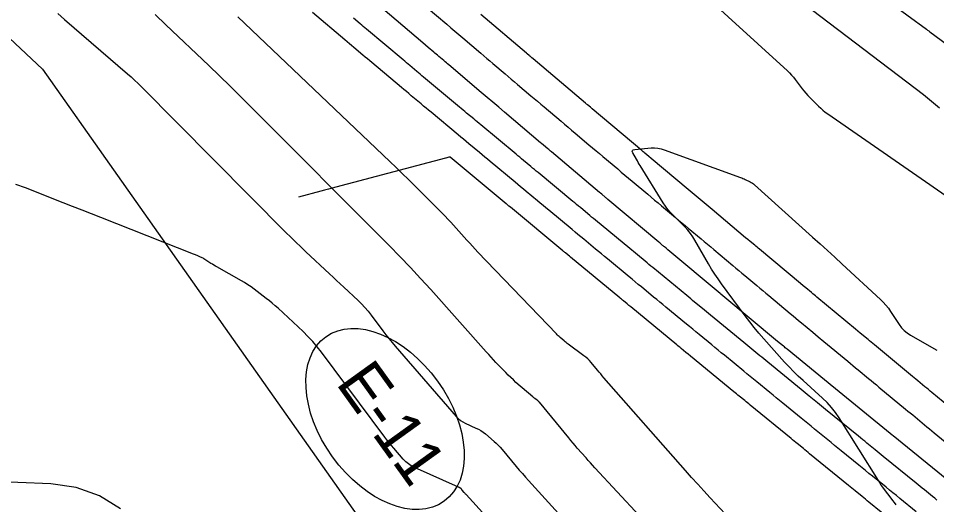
# Model space of a CAD drawing. Extents: x 1005228 to 1008882, y 1883389 to 1885754.
# Drawn here: x 1007392.6 to 1007516.7, y 1884970.9 to 1885036.6 of the extents above; entities that cross this region are included whole.
import ezdxf

# ---------------------------------------------------------------- set-up
doc = ezdxf.new("R2010")
doc.units = 0
for name, color, linetype in [('ATDIMS', 7, 'Continuous'), ('C-ANNO-NOTE', 7, 'Continuous'), ('R_Erosion', 7, 'Continuous'), ('S_BRIDGE', 7, 'Continuous'), ('TSOBSTACLE', 7, 'Continuous')]:
    doc.layers.add(name, color=color, linetype=linetype)

msp = doc.modelspace()

# ---------------------------------------------------------------- linework, layer by layer
at = {"layer": 'ATDIMS'}
msp.add_lwpolyline([(1007518.11, 1884974.26), (1007510.87, 1884980.13), (1007510.8, 1884980.19), (1007510.73, 1884980.24), (1007510.46, 1884980.47), (1007503.05, 1884986.51), (1007503, 1884986.55), (1007502.85, 1884986.68), (1007496.52, 1884991.85), (1007496.4, 1884991.95), (1007496.27, 1884992.05), (1007496.15, 1884992.16), (1007496.02, 1884992.26), (1007495.24, 1884992.91), (1007495.23, 1884992.92), (1007487.84, 1884999.08), (1007487.58, 1884999.29), (1007487.52, 1884999.34), (1007487.46, 1884999.4), (1007480.41, 1885005.29), (1007480.17, 1885005.49), (1007479.93, 1885005.69), (1007479.87, 1885005.74), (1007479.81, 1885005.79), (1007479.75, 1885005.84), (1007479.69, 1885005.89), (1007479.3, 1885006.22), (1007479.18, 1885006.33), (1007472.3, 1885012.1), (1007472.21, 1885012.18), (1007472.11, 1885012.26), (1007472.02, 1885012.33), (1007471.93, 1885012.41), (1007471.46, 1885012.8), (1007471.28, 1885012.96), (1007471.18, 1885013.04), (1007464.67, 1885018.52), (1007464.55, 1885018.63), (1007464.43, 1885018.73), (1007464.3, 1885018.83), (1007464.18, 1885018.94), (1007463.57, 1885019.45), (1007463.32, 1885019.66), (1007463.2, 1885019.76), (1007458.33, 1885023.88), (1007457.54, 1885024.55), (1007456.75, 1885025.22), (1007455.96, 1885025.89), (1007455.18, 1885026.55), (1007450.8, 1885030.27), (1007450.63, 1885030.41), (1007450.46, 1885030.56), (1007450.29, 1885030.7), (1007450.11, 1885030.85), (1007449.43, 1885031.43), (1007449.26, 1885031.57), (1007449.09, 1885031.72), (1007448.92, 1885031.86), (1007448.75, 1885032.01), (1007448, 1885032.64), (1007447.64, 1885032.95), (1007447.28, 1885033.26), (1007441.86, 1885037.87)], dxfattribs=at)
at = {"layer": 'C-ANNO-NOTE'}
for points in [[(1007517.13, 1885024.43), (1007516.05, 1885025.33), (1007514.96, 1885026.21), (1007513.85, 1885027.07), (1007499.96, 1885037.62)], [(1007397.92, 1885037.21), (1007398.85, 1885036.41), (1007407.34, 1885029.08), (1007407.83, 1885028.65), (1007408.31, 1885028.21), (1007408.78, 1885027.76), (1007409.24, 1885027.3), (1007428.76, 1885007.65), (1007429.43, 1885006.99), (1007430.11, 1885006.33), (1007430.79, 1885005.67), (1007431.48, 1885005.02), (1007434.65, 1885002.06), (1007435.14, 1885001.61), (1007435.62, 1885001.16), (1007436.1, 1885000.7), (1007436.59, 1885000.25), (1007438.52, 1884998.45), (1007439, 1884997.98), (1007439.45, 1884997.5), (1007439.88, 1884997), (1007440.28, 1884996.48), (1007441.87, 1884994.35), (1007442.28, 1884993.82), (1007442.69, 1884993.3), (1007443.11, 1884992.78), (1007443.54, 1884992.28), (1007451.78, 1884982.77), (1007452.05, 1884982.49), (1007452.35, 1884982.24), (1007452.67, 1884982.03), (1007453.01, 1884981.86), (1007454.46, 1884981.21), (1007454.81, 1884981.05), (1007455.13, 1884980.85), (1007455.45, 1884980.64), (1007455.74, 1884980.4), (1007456.91, 1884979.4), (1007457.19, 1884979.14), (1007457.47, 1884978.88), (1007457.73, 1884978.6), (1007457.98, 1884978.31), (1007459.91, 1884976), (1007460.32, 1884975.52), (1007460.73, 1884975.04), (1007461.15, 1884974.57), (1007461.57, 1884974.1), (1007466.98, 1884968.15)], [(1007488.63, 1884956.35), (1007470.54, 1884975.84), (1007470.23, 1884976.17), (1007469.93, 1884976.5), (1007469.64, 1884976.83), (1007469.34, 1884977.16), (1007468.16, 1884978.5), (1007467.87, 1884978.84), (1007467.58, 1884979.18), (1007467.29, 1884979.52), (1007467.01, 1884979.86), (1007463.03, 1884984.68), (1007462.97, 1884984.75), (1007462.9, 1884984.82), (1007462.83, 1884984.89), (1007462.75, 1884984.95), (1007462.44, 1884985.18), (1007462.36, 1884985.24), (1007462.28, 1884985.3), (1007462.21, 1884985.36), (1007462.13, 1884985.42), (1007459.87, 1884987.38), (1007459.52, 1884987.7), (1007459.17, 1884988.03), (1007458.82, 1884988.36), (1007458.49, 1884988.7), (1007457.16, 1884990.08), (1007456.83, 1884990.43), (1007456.51, 1884990.78), (1007456.18, 1884991.13), (1007455.86, 1884991.49), (1007448.35, 1884999.91), (1007446.98, 1885001.42), (1007445.6, 1885002.92), (1007444.19, 1885004.39), (1007442.76, 1885005.84), (1007424.06, 1885024.58), (1007422.64, 1885026), (1007421.21, 1885027.4), (1007419.78, 1885028.79), (1007418.33, 1885030.18), (1007412.53, 1885035.71), (1007411.09, 1885037.09)], [(1007511.27, 1884970.84), (1007511.03, 1884971.13), (1007510.8, 1884971.41), (1007510.57, 1884971.71), (1007509.69, 1884972.9), (1007509.47, 1884973.2), (1007509.26, 1884973.5), (1007509.06, 1884973.81), (1007508.86, 1884974.12), (1007503.56, 1884982.58), (1007503.07, 1884983.31), (1007502.53, 1884984), (1007501.95, 1884984.65), (1007501.31, 1884985.26), (1007498.68, 1884987.62), (1007498.03, 1884988.22), (1007497.4, 1884988.84), (1007496.79, 1884989.47), (1007496.19, 1884990.12), (1007493.38, 1884993.27), (1007492.72, 1884994.02), (1007492.09, 1884994.78), (1007491.47, 1884995.57), (1007490.86, 1884996.36), (1007487.66, 1885000.7), (1007487.19, 1885001.35), (1007486.74, 1885002.02), (1007486.32, 1885002.69), (1007485.91, 1885003.38), (1007484.06, 1885006.58), (1007483.77, 1885007.05), (1007483.45, 1885007.5), (1007483.1, 1885007.93), (1007482.72, 1885008.33), (1007481.15, 1885009.91), (1007480.77, 1885010.31), (1007480.42, 1885010.73), (1007480.09, 1885011.18), (1007479.78, 1885011.64), (1007476.66, 1885016.67), (1007476.53, 1885016.88), (1007476.4, 1885017.09), (1007476.28, 1885017.31), (1007476.16, 1885017.52), (1007475.67, 1885018.38), (1007475.59, 1885018.57), (1007475.61, 1885018.71), (1007475.72, 1885018.81), (1007475.92, 1885018.85), (1007478.15, 1885019.05), (1007478.6, 1885019.07), (1007479.04, 1885019.03), (1007479.48, 1885018.95), (1007479.91, 1885018.82), (1007490.21, 1885015.08), (1007490.38, 1885015.01), (1007490.55, 1885014.94), (1007490.71, 1885014.87), (1007490.87, 1885014.79), (1007491.52, 1885014.47), (1007491.68, 1885014.39), (1007491.83, 1885014.29), (1007491.98, 1885014.19), (1007492.11, 1885014.07), (1007499.96, 1885007.01), (1007500.97, 1885006.1), (1007501.97, 1885005.19), (1007502.97, 1885004.28), (1007503.96, 1885003.36), (1007509.15, 1884998.58), (1007509.53, 1884998.21), (1007509.88, 1884997.82), (1007510.21, 1884997.4), (1007510.52, 1884996.97), (1007511.68, 1884995.18), (1007511.99, 1884994.76), (1007512.35, 1884994.38), (1007512.75, 1884994.05), (1007513.19, 1884993.77), (1007516.77, 1884991.74)], [(1007471.72, 1884951.77), (1007453.12, 1884972.21), (1007453.06, 1884972.28), (1007453, 1884972.34), (1007452.94, 1884972.41), (1007452.88, 1884972.48), (1007452.61, 1884972.81), (1007452.57, 1884972.85), (1007452.53, 1884972.89), (1007452.49, 1884972.93), (1007452.45, 1884972.97), (1007452.29, 1884973.11), (1007452.24, 1884973.15), (1007452.2, 1884973.18), (1007452.15, 1884973.2), (1007452.1, 1884973.23), (1007446.15, 1884975.87), (1007445.72, 1884976.09), (1007445.33, 1884976.35), (1007444.96, 1884976.65), (1007444.63, 1884977), (1007443.35, 1884978.47), (1007443.04, 1884978.84), (1007442.73, 1884979.21), (1007442.43, 1884979.59), (1007442.13, 1884979.98), (1007433.58, 1884991.45), (1007433, 1884992.19), (1007432.39, 1884992.91), (1007431.75, 1884993.59), (1007431.08, 1884994.25), (1007427.7, 1884997.4), (1007427.32, 1884997.74), (1007426.93, 1884998.08), (1007426.53, 1884998.41), (1007426.12, 1884998.73), (1007424.47, 1884999.98), (1007424.06, 1885000.28), (1007423.63, 1885000.57), (1007423.19, 1885000.85), (1007422.75, 1885001.11), (1007419.43, 1885002.98), (1007419.23, 1885003.09), (1007419.03, 1885003.21), (1007418.83, 1885003.33), (1007418.64, 1885003.46), (1007417.68, 1885004.07), (1007417.57, 1885004.14), (1007417.46, 1885004.2), (1007417.35, 1885004.26), (1007417.23, 1885004.31), (1007416.76, 1885004.51), (1007416.65, 1885004.56), (1007416.53, 1885004.61), (1007416.41, 1885004.66), (1007416.29, 1885004.71), (1007403.76, 1885009.64), (1007402.49, 1885010.14), (1007401.21, 1885010.64), (1007399.93, 1885011.14), (1007398.66, 1885011.64), (1007393.55, 1885013.65), (1007392.26, 1885014.12)], [(1007406.39, 1884970.28), (1007403.57, 1884972.05), (1007400.43, 1884973.18), (1007396.98, 1884973.65), (1007365.73, 1884974.94), (1007364.86, 1884975), (1007364, 1884975.1), (1007363.14, 1884975.23), (1007362.29, 1884975.41), (1007358.9, 1884976.21), (1007358.07, 1884976.45), (1007357.28, 1884976.76), (1007356.52, 1884977.16), (1007355.81, 1884977.65), (1007334.74, 1884993.36), (1007333.77, 1884993.99), (1007332.75, 1884994.47), (1007331.67, 1884994.8), (1007330.54, 1884994.99), (1007325.89, 1884995.44), (1007324.72, 1884995.56), (1007323.57, 1884995.71)]]:
    msp.add_lwpolyline(points, dxfattribs=at)
at = {"layer": 'R_Erosion'}
msp.add_lwpolyline([(1007330.25, 1885091.31), (1007395.85, 1885029.7), (1007508, 1884870.74), (1007444.37, 1884775.26), (1007458.35, 1884766.85)], dxfattribs=at)
msp.add_ellipse((1007442.17, 1884982.43), major_axis=(8, -11.12), ratio=0.638788, dxfattribs=at)
at = {"layer": 'S_BRIDGE'}
for points in [[(1007484.55, 1885040.45), (1007496.57, 1885029.47), (1007496.85, 1885029.2), (1007497.12, 1885028.91), (1007497.37, 1885028.62), (1007497.62, 1885028.31), (1007498.56, 1885027.06), (1007498.8, 1885026.75), (1007499.05, 1885026.45), (1007499.31, 1885026.16), (1007499.58, 1885025.88), (1007500.77, 1885024.7), (1007501.06, 1885024.42), (1007501.37, 1885024.15), (1007501.69, 1885023.9), (1007502.02, 1885023.66), (1007518.62, 1885012.17)], [(1007489.49, 1884968.16), (1007486.12, 1884971.79), (1007485.28, 1884972.7), (1007484.45, 1884973.61), (1007483.62, 1884974.53), (1007482.8, 1884975.46), (1007471.76, 1884988.01), (1007471.54, 1884988.26), (1007471.32, 1884988.51), (1007471.1, 1884988.77), (1007470.89, 1884989.03), (1007470.03, 1884990.06), (1007469.81, 1884990.31), (1007469.58, 1884990.55), (1007469.33, 1884990.77), (1007469.06, 1884990.98), (1007466.93, 1884992.54), (1007466.79, 1884992.64), (1007466.65, 1884992.75), (1007466.52, 1884992.86), (1007466.38, 1884992.98), (1007465.85, 1884993.44), (1007465.71, 1884993.56), (1007465.59, 1884993.68), (1007465.46, 1884993.8), (1007465.33, 1884993.93), (1007454.73, 1885004.98), (1007454.35, 1885005.38), (1007453.98, 1885005.78), (1007453.61, 1885006.18), (1007453.24, 1885006.59), (1007451.79, 1885008.22), (1007451.42, 1885008.63), (1007451.05, 1885009.03), (1007450.67, 1885009.43), (1007450.28, 1885009.82), (1007446.14, 1885013.97), (1007445.32, 1885014.79), (1007444.5, 1885015.6), (1007443.66, 1885016.41), (1007442.83, 1885017.21), (1007422.28, 1885036.79)]]:
    msp.add_lwpolyline(points, dxfattribs=at)
at = {"layer": 'TSOBSTACLE'}
for points in [[(1007509.18, 1885039.67), (1007513.9, 1885036.18), (1007514.39, 1885035.82), (1007515.19, 1885035.22), (1007515.35, 1885035.1), (1007515.51, 1885034.98), (1007515.68, 1885034.87), (1007515.84, 1885034.75), (1007521.64, 1885030.48)], [(1007513.99, 1884969.87), (1007511.75, 1884971.69), (1007511.29, 1884972.07), (1007510.82, 1884972.44), (1007510.36, 1884972.82), (1007509.9, 1884973.2), (1007508.05, 1884974.7), (1007507.58, 1884975.07), (1007507.12, 1884975.45), (1007506.66, 1884975.83), (1007506.2, 1884976.2), (1007503.85, 1884978.12), (1007503.39, 1884978.49), (1007502.94, 1884978.86), (1007502.49, 1884979.23), (1007502.04, 1884979.59), (1007500.23, 1884981.07), (1007499.78, 1884981.44), (1007499.32, 1884981.81), (1007498.87, 1884982.18), (1007498.42, 1884982.55), (1007495.95, 1884984.57), (1007495.5, 1884984.93), (1007495.06, 1884985.29), (1007494.62, 1884985.65), (1007494.18, 1884986.01), (1007492.42, 1884987.45), (1007491.98, 1884987.82), (1007491.54, 1884988.18), (1007491.1, 1884988.54), (1007490.66, 1884988.9), (1007488.04, 1884991.04), (1007487.62, 1884991.39), (1007487.19, 1884991.75), (1007486.76, 1884992.1), (1007486.33, 1884992.45), (1007484.62, 1884993.86), (1007484.19, 1884994.21), (1007483.76, 1884994.56), (1007483.33, 1884994.91), (1007482.9, 1884995.26), (1007480.14, 1884997.54), (1007479.72, 1884997.88), (1007479.31, 1884998.23), (1007478.89, 1884998.57), (1007478.48, 1884998.91), (1007476.82, 1885000.27), (1007476.41, 1885000.61), (1007476, 1885000.96), (1007475.58, 1885001.3), (1007475.17, 1885001.64), (1007472.22, 1885004.07), (1007471.83, 1885004.4), (1007471.43, 1885004.73), (1007471.03, 1885005.06), (1007470.63, 1885005.39), (1007469.04, 1885006.71), (1007468.64, 1885007.04), (1007468.24, 1885007.36), (1007467.85, 1885007.69), (1007467.45, 1885008.02), (1007464.3, 1885010.64), (1007463.92, 1885010.95), (1007463.54, 1885011.27), (1007463.16, 1885011.58), (1007462.78, 1885011.9), (1007461.26, 1885013.16), (1007460.88, 1885013.47), (1007460.5, 1885013.79), (1007460.12, 1885014.1), (1007459.74, 1885014.42), (1007456.36, 1885017.24), (1007456, 1885017.53), (1007455.64, 1885017.83), (1007455.28, 1885018.13), (1007454.92, 1885018.43), (1007453.49, 1885019.63), (1007453.13, 1885019.92), (1007452.77, 1885020.22), (1007452.41, 1885020.52), (1007452.06, 1885020.82), (1007448.4, 1885023.88), (1007448.06, 1885024.16), (1007447.73, 1885024.44), (1007447.39, 1885024.72), (1007447.06, 1885025), (1007445.72, 1885026.11), (1007445.39, 1885026.39), (1007445.05, 1885026.67), (1007444.72, 1885026.95), (1007444.39, 1885027.23), (1007440.4, 1885030.58), (1007440.09, 1885030.83), (1007439.79, 1885031.09), (1007439.48, 1885031.34), (1007439.18, 1885031.6), (1007437.96, 1885032.62), (1007437.65, 1885032.88), (1007437.35, 1885033.14), (1007437.04, 1885033.39), (1007436.74, 1885033.65), (1007432.35, 1885037.34)], [(1007447.75, 1885038.11), (1007450.5, 1885035.76), (1007451.05, 1885035.3), (1007451.59, 1885034.84), (1007452.13, 1885034.38), (1007452.67, 1885033.92), (1007455.1, 1885031.87), (1007455.51, 1885031.51), (1007455.93, 1885031.16), (1007456.34, 1885030.81), (1007456.76, 1885030.46), (1007458.41, 1885029.05), (1007458.83, 1885028.7), (1007459.24, 1885028.35), (1007459.66, 1885027.99), (1007460.08, 1885027.64), (1007461.89, 1885026.11), (1007462.33, 1885025.73), (1007462.77, 1885025.36), (1007463.22, 1885024.99), (1007463.66, 1885024.62), (1007465.97, 1885022.66), (1007466.44, 1885022.26), (1007466.91, 1885021.86), (1007467.39, 1885021.46), (1007467.86, 1885021.07), (1007469.74, 1885019.48), (1007470.21, 1885019.08), (1007470.69, 1885018.68), (1007471.16, 1885018.29), (1007471.63, 1885017.89), (1007473.62, 1885016.22), (1007474.11, 1885015.8), (1007474.59, 1885015.39), (1007475.08, 1885014.98), (1007475.57, 1885014.57), (1007477.69, 1885012.79), (1007478.15, 1885012.41), (1007478.61, 1885012.02), (1007479.07, 1885011.64), (1007479.53, 1885011.25), (1007481.42, 1885009.66), (1007481.85, 1885009.3), (1007482.29, 1885008.94), (1007482.72, 1885008.57), (1007483.15, 1885008.21), (1007484.89, 1885006.76), (1007485.32, 1885006.4), (1007485.75, 1885006.03), (1007486.19, 1885005.67), (1007486.62, 1885005.31), (1007489.18, 1885003.17), (1007489.59, 1885002.83), (1007489.99, 1885002.49), (1007490.4, 1885002.15), (1007490.8, 1885001.81), (1007492.43, 1885000.46), (1007492.83, 1885000.12), (1007493.24, 1884999.78), (1007493.64, 1884999.44), (1007494.05, 1884999.11), (1007496.95, 1884996.69), (1007497.33, 1884996.37), (1007497.71, 1884996.06), (1007498.08, 1884995.75), (1007498.46, 1884995.43), (1007499.98, 1884994.17), (1007500.73, 1884993.54), (1007501.49, 1884992.92), (1007504.73, 1884990.22), (1007505.08, 1884989.93), (1007505.43, 1884989.64), (1007505.78, 1884989.35), (1007506.13, 1884989.06), (1007507.54, 1884987.9), (1007507.89, 1884987.61), (1007508.24, 1884987.32), (1007508.59, 1884987.03), (1007508.94, 1884986.74), (1007512.53, 1884983.77), (1007512.85, 1884983.5), (1007513.17, 1884983.24), (1007513.5, 1884982.97), (1007513.82, 1884982.7), (1007515.11, 1884981.64), (1007515.43, 1884981.37), (1007515.76, 1884981.1), (1007516.08, 1884980.84), (1007516.4, 1884980.57), (1007519.63, 1884977.91)], [(1007516.77, 1884971.48), (1007516.49, 1884971.71), (1007516.2, 1884971.94), (1007515.08, 1884972.85), (1007514.8, 1884973.08), (1007514.51, 1884973.31), (1007514.23, 1884973.54), (1007513.95, 1884973.77), (1007509.52, 1884977.37), (1007509.24, 1884977.59), (1007508.96, 1884977.82), (1007508.68, 1884978.05), (1007508.41, 1884978.27), (1007507.29, 1884979.18), (1007507.01, 1884979.41), (1007506.74, 1884979.63), (1007506.46, 1884979.86), (1007506.18, 1884980.09), (1007501.72, 1884983.72), (1007501.44, 1884983.95), (1007501.17, 1884984.17), (1007500.89, 1884984.4), (1007500.62, 1884984.62), (1007499.52, 1884985.52), (1007499.25, 1884985.74), (1007498.97, 1884985.97), (1007498.7, 1884986.19), (1007498.42, 1884986.42), (1007493.93, 1884990.1), (1007493.66, 1884990.32), (1007493.39, 1884990.54), (1007493.11, 1884990.76), (1007492.84, 1884990.98), (1007491.76, 1884991.87), (1007491.49, 1884992.09), (1007491.22, 1884992.31), (1007490.95, 1884992.54), (1007490.68, 1884992.76), (1007486.15, 1884996.48), (1007485.88, 1884996.7), (1007485.61, 1884996.92), (1007485.35, 1884997.14), (1007485.08, 1884997.36), (1007484.02, 1884998.23), (1007483.75, 1884998.45), (1007483.49, 1884998.67), (1007483.22, 1884998.89), (1007482.96, 1884999.11), (1007478.38, 1885002.88), (1007478.11, 1885003.1), (1007477.85, 1885003.31), (1007477.59, 1885003.53), (1007477.33, 1885003.74), (1007476.29, 1885004.6), (1007476.03, 1885004.82), (1007475.77, 1885005.04), (1007475.51, 1885005.25), (1007475.25, 1885005.47), (1007470.61, 1885009.3), (1007470.36, 1885009.51), (1007470.1, 1885009.72), (1007469.85, 1885009.93), (1007469.6, 1885010.14), (1007468.58, 1885010.99), (1007468.32, 1885011.2), (1007468.07, 1885011.41), (1007467.81, 1885011.62), (1007467.56, 1885011.83), (1007462.86, 1885015.72), (1007462.62, 1885015.93), (1007462.37, 1885016.14), (1007462.12, 1885016.34), (1007461.87, 1885016.55), (1007460.88, 1885017.38), (1007460.63, 1885017.58), (1007460.38, 1885017.79), (1007460.13, 1885018), (1007459.89, 1885018.2), (1007455.12, 1885022.17), (1007454.88, 1885022.37), (1007454.64, 1885022.57), (1007454.4, 1885022.77), (1007454.16, 1885022.97), (1007453.2, 1885023.77), (1007452.96, 1885023.97), (1007452.72, 1885024.18), (1007452.48, 1885024.38), (1007452.24, 1885024.58), (1007447.39, 1885028.63), (1007447.16, 1885028.82), (1007446.93, 1885029.02), (1007446.7, 1885029.21), (1007446.47, 1885029.4), (1007445.54, 1885030.18), (1007445.31, 1885030.37), (1007445.08, 1885030.56), (1007444.85, 1885030.76), (1007444.62, 1885030.95), (1007439.67, 1885035.11), (1007439.45, 1885035.29), (1007439.23, 1885035.48), (1007439.01, 1885035.66), (1007438.79, 1885035.84), (1007437.91, 1885036.58)], [(1007520.68, 1884982.23), (1007516.11, 1884986), (1007515.87, 1884986.2), (1007515.63, 1884986.4), (1007515.39, 1884986.59), (1007515.15, 1884986.79), (1007514.18, 1884987.59), (1007513.94, 1884987.79), (1007513.7, 1884987.99), (1007513.46, 1884988.19), (1007513.22, 1884988.39), (1007508.32, 1884992.44), (1007508.11, 1884992.62), (1007507.89, 1884992.8), (1007507.68, 1884992.97), (1007507.47, 1884993.15), (1007506.41, 1884994.03), (1007505.77, 1884994.56), (1007500.54, 1884998.9), (1007500.36, 1884999.06), (1007500.17, 1884999.21), (1007499.99, 1884999.36), (1007499.8, 1884999.52), (1007499.07, 1885000.13), (1007498.7, 1885000.43), (1007498.33, 1885000.74), (1007492.77, 1885005.38), (1007492.62, 1885005.51), (1007492.46, 1885005.64), (1007492.31, 1885005.77), (1007492.15, 1885005.9), (1007491.53, 1885006.42), (1007491.22, 1885006.68), (1007490.91, 1885006.93), (1007486.38, 1885010.73), (1007485.57, 1885011.4), (1007484.76, 1885012.08), (1007483.96, 1885012.75), (1007483.15, 1885013.43), (1007478.13, 1885017.65), (1007477.81, 1885017.91), (1007477.29, 1885018.35), (1007477.18, 1885018.44), (1007477.08, 1885018.53), (1007476.97, 1885018.62), (1007476.87, 1885018.71), (1007470.15, 1885024.36), (1007469.93, 1885024.55), (1007469.55, 1885024.87), (1007469.48, 1885024.93), (1007469.4, 1885024.99), (1007469.33, 1885025.06), (1007469.25, 1885025.12), (1007462.19, 1885031.09), (1007462.01, 1885031.24), (1007461.82, 1885031.4), (1007461.78, 1885031.44), (1007461.74, 1885031.47), (1007461.69, 1885031.51), (1007461.65, 1885031.55), (1007461.4, 1885031.76), (1007461.31, 1885031.84), (1007455.11, 1885037.1)], [(1007512.59, 1884967.14), (1007507.59, 1884971.2), (1007507.36, 1884971.39), (1007507.13, 1884971.58), (1007506.9, 1884971.77), (1007506.67, 1884971.95), (1007505.74, 1884972.71), (1007505.51, 1884972.89), (1007505.28, 1884973.08), (1007505.05, 1884973.27), (1007504.82, 1884973.46), (1007499.57, 1884977.74), (1007499.36, 1884977.91), (1007499.15, 1884978.08), (1007498.94, 1884978.25), (1007498.73, 1884978.42), (1007497.89, 1884979.1), (1007497.69, 1884979.27), (1007497.48, 1884979.44), (1007497.27, 1884979.61), (1007497.06, 1884979.78), (1007491.52, 1884984.31), (1007491.34, 1884984.46), (1007491.16, 1884984.61), (1007490.97, 1884984.76), (1007490.79, 1884984.91), (1007490.05, 1884985.51), (1007489.87, 1884985.66), (1007489.69, 1884985.81), (1007489.5, 1884985.96), (1007489.32, 1884986.11), (1007483.46, 1884990.92), (1007483.15, 1884991.18), (1007482.84, 1884991.43), (1007482.22, 1884991.94), (1007482.06, 1884992.07), (1007481.91, 1884992.2), (1007481.75, 1884992.33), (1007481.6, 1884992.46), (1007475.38, 1884997.58), (1007475.13, 1884997.78), (1007474.88, 1884997.98), (1007474.39, 1884998.39), (1007474.26, 1884998.5), (1007474.14, 1884998.6), (1007474.01, 1884998.7), (1007473.89, 1884998.8), (1007467.26, 1885004.28), (1007467.09, 1885004.43), (1007466.91, 1885004.57), (1007466.56, 1885004.86), (1007466.47, 1885004.94), (1007466.38, 1885005.01), (1007466.29, 1885005.08), (1007466.2, 1885005.16), (1007459.11, 1885011.04), (1007458.92, 1885011.2), (1007458.73, 1885011.36), (1007458.68, 1885011.4), (1007458.64, 1885011.44), (1007458.59, 1885011.48), (1007458.54, 1885011.52), (1007450.98, 1885017.81), (1007450.97, 1885017.82), (1007450.95, 1885017.82), (1007450.94, 1885017.83), (1007450.93, 1885017.82), (1007450.86, 1885017.8), (1007450.81, 1885017.79), (1007450.37, 1885017.68), (1007450.32, 1885017.66), (1007435.52, 1885013.75), (1007435.01, 1885013.62), (1007434.51, 1885013.48), (1007434, 1885013.35), (1007433.5, 1885013.22), (1007430.46, 1885012.41)]]:
    msp.add_lwpolyline(points, dxfattribs=at)

# ---------------------------------------------------------------- texts
at = {"layer": 'R_Erosion'}
msp.add_text('E-11', height=6.25, rotation=305.719, dxfattribs=at).set_placement((1007435.41, 1884987.27))

doc.saveas('drawing.dxf')
